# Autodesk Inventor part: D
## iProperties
Created: 2007-08
Part Number: D
Document SubType Name: Modeling
Designer: t-ikumi
Density: 1 g/cm^3
Author: t-ikumi
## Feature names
1. 押し出し1 [Extrusion]
2. 押し出し2 [Extrusion]
3. フィレット1 [Fillet]
4. 押し出し3 [Extrusion]
5. 面取り1 [Chamfer]
6. 面取り2 [Chamfer]
